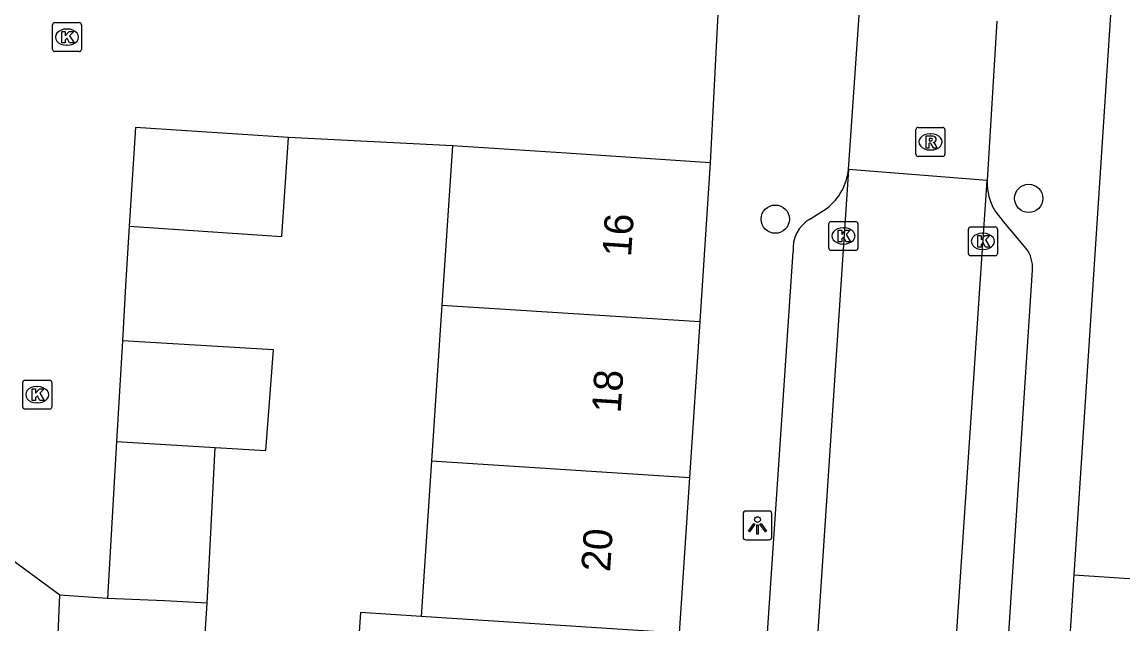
# Model space of a CAD drawing. Extents: x 160356 to 161355, y 381727 to 382845.
# Drawn here: x 160534.35 to 160572.44, y 382168.23 to 382189.04 of the extents above; entities that cross this region are included whole.
import ezdxf

# ---------------------------------------------------------------- set-up
doc = ezdxf.new("R2010")
doc.units = 0
for name, color, linetype in [('IMGEO_Boom', 7, 'Continuous'), ('IMGEO_Kolk', 7, 'Continuous'), ('IMGEO_Lichtpunt', 7, 'Continuous'), ('IMGEO_Pand', 7, 'Continuous'), ('IMGEO_Pand_nummerreeks', 7, 'Continuous'), ('IMGEO_Rijbaan_lokaal_open', 7, 'Continuous'), ('IMGEO_Rioolput', 7, 'Continuous'), ('IMGEO_Voetpad_open', 7, 'Continuous')]:
    doc.layers.add(name, color=color, linetype=linetype)

msp = doc.modelspace()

# ---------------------------------------------------------------- linework, layer by layer
at = {"layer": 'IMGEO_Boom'}
for centre in [(160569.175, 382182.943), (160560.409, 382182.225)]:
    msp.add_circle(centre, 0.489, dxfattribs=at)
at = {"layer": 'IMGEO_Kolk'}
for p, q in [((160535.48, 382189.019), (160536.332, 382189.019)), ((160535.405, 382188.093), (160535.405, 382188.945)), ((160535.893, 382188.799), (160535.918, 382188.799)), ((160536.406, 382188.945), (160536.406, 382188.093)), ((160535.916, 382188.239), (160535.891, 382188.239)), ((160536.332, 382188.019), (160535.48, 382188.019)), ((160562.339, 382182.144), (160563.191, 382182.144)), ((160562.264, 382181.218), (160562.264, 382182.07)), ((160562.752, 382181.924), (160562.777, 382181.924)), ((160563.265, 382182.07), (160563.265, 382181.218)), ((160567.09, 382181.031), (160567.09, 382181.883)), ((160567.165, 382181.957), (160568.017, 382181.957)), ((160568.091, 382181.883), (160568.091, 382181.031)), ((160562.775, 382181.364), (160562.75, 382181.364)), ((160567.578, 382181.737), (160567.603, 382181.737)), ((160563.191, 382181.144), (160562.339, 382181.144)), ((160567.601, 382181.177), (160567.576, 382181.177)), ((160568.017, 382180.957), (160567.165, 382180.957)), ((160534.377, 382175.73), (160534.377, 382176.582)), ((160534.452, 382176.656), (160535.304, 382176.656)), ((160534.865, 382176.436), (160534.89, 382176.436)), ((160535.378, 382176.582), (160535.378, 382175.73)), ((160535.304, 382175.656), (160534.452, 382175.656)), ((160534.888, 382175.876), (160534.863, 382175.876))]:
    msp.add_line(p, q, dxfattribs=at)
for points in [[(160535.48, 382189.019), (160536.332, 382189.019)], [(160535.405, 382188.093), (160535.405, 382188.945)], [(160535.726, 382188.719), (160535.849, 382188.719), (160535.849, 382188.568), (160535.979, 382188.719), (160536.143, 382188.719), (160535.997, 382188.568), (160536.15, 382188.319), (160535.998, 382188.319), (160535.913, 382188.483), (160535.849, 382188.416), (160535.849, 382188.319), (160535.726, 382188.319), (160535.726, 382188.719)], [(160536.406, 382188.945), (160536.406, 382188.093)], [(160536.332, 382188.019), (160535.48, 382188.019)], [(160562.339, 382182.144), (160563.191, 382182.144)], [(160562.264, 382181.218), (160562.264, 382182.07)], [(160562.585, 382181.844), (160562.708, 382181.844), (160562.708, 382181.693), (160562.838, 382181.844), (160563.002, 382181.844), (160562.856, 382181.693), (160563.009, 382181.444), (160562.857, 382181.444), (160562.772, 382181.608), (160562.708, 382181.541), (160562.708, 382181.444), (160562.585, 382181.444), (160562.585, 382181.844)], [(160563.265, 382182.07), (160563.265, 382181.218)], [(160567.09, 382181.031), (160567.09, 382181.883)], [(160567.165, 382181.957), (160568.017, 382181.957)], [(160568.091, 382181.883), (160568.091, 382181.031)], [(160567.411, 382181.657), (160567.534, 382181.657), (160567.534, 382181.506), (160567.664, 382181.657), (160567.828, 382181.657), (160567.682, 382181.506), (160567.835, 382181.257), (160567.683, 382181.257), (160567.598, 382181.421), (160567.534, 382181.354), (160567.534, 382181.257), (160567.411, 382181.257), (160567.411, 382181.657)], [(160563.191, 382181.144), (160562.339, 382181.144)], [(160568.017, 382180.957), (160567.165, 382180.957)], [(160534.377, 382175.73), (160534.377, 382176.582)], [(160534.452, 382176.656), (160535.304, 382176.656)], [(160535.378, 382176.582), (160535.378, 382175.73)], [(160534.698, 382176.356), (160534.821, 382176.356), (160534.821, 382176.205), (160534.951, 382176.356), (160535.115, 382176.356), (160534.969, 382176.205), (160535.122, 382175.956), (160534.97, 382175.956), (160534.885, 382176.12), (160534.821, 382176.053), (160534.821, 382175.956), (160534.698, 382175.956), (160534.698, 382176.356)], [(160535.304, 382175.656), (160534.452, 382175.656)]]:
    msp.add_lwpolyline(points, dxfattribs=at)
for centre, start, end in [((160535.482, 382188.943), 91.552, 178.448), ((160535.482, 382188.943), 91.552, 178.448), ((160536.33, 382188.943), 1.552, 88.448), ((160536.33, 382188.943), 1.552, 88.448), ((160535.482, 382188.095), 181.552, 268.448), ((160535.482, 382188.095), 181.552, 268.448), ((160536.33, 382188.095), 271.552, 358.448), ((160536.33, 382188.095), 271.552, 358.448), ((160562.341, 382182.068), 91.552, 178.448), ((160562.341, 382182.068), 91.552, 178.448), ((160563.189, 382182.068), 1.552, 88.448), ((160563.189, 382182.068), 1.552, 88.448), ((160567.167, 382181.881), 91.552, 178.448), ((160567.167, 382181.881), 91.552, 178.448), ((160568.015, 382181.881), 1.552, 88.448), ((160568.015, 382181.881), 1.552, 88.448), ((160562.341, 382181.22), 181.552, 268.448), ((160562.341, 382181.22), 181.552, 268.448), ((160563.189, 382181.22), 271.552, 358.448), ((160563.189, 382181.22), 271.552, 358.448), ((160567.167, 382181.033), 181.552, 268.448), ((160567.167, 382181.033), 181.552, 268.448), ((160568.015, 382181.033), 271.552, 358.448), ((160568.015, 382181.033), 271.552, 358.448), ((160534.454, 382176.58), 91.552, 178.448), ((160534.454, 382176.58), 91.552, 178.448), ((160535.302, 382176.58), 1.552, 88.448), ((160535.302, 382176.58), 1.552, 88.448), ((160534.454, 382175.732), 181.552, 268.448), ((160534.454, 382175.732), 181.552, 268.448), ((160535.302, 382175.732), 271.552, 358.448), ((160535.302, 382175.732), 271.552, 358.448)]:
    msp.add_arc(centre, 0.0765, start, end, dxfattribs=at)
for centre, major_axis, ratio, start_param, end_param in [((160535.892, 382188.519), (-0.387, 0.002), 0.722429, 4.712389, 7.853982), ((160535.917, 382188.519), (-0.39, 0.002), 0.717154, 1.570796, 4.712389), ((160562.751, 382181.644), (-0.387, 0.002), 0.722429, 4.712389, 7.853982), ((160562.776, 382181.644), (-0.39, 0.002), 0.717154, 1.570796, 4.712389), ((160567.577, 382181.457), (-0.387, 0.002), 0.722429, 4.712389, 7.853982), ((160567.602, 382181.457), (-0.39, 0.002), 0.717154, 1.570796, 4.712389), ((160534.864, 382176.156), (-0.387, 0.002), 0.722429, 4.712389, 7.853982), ((160534.889, 382176.156), (-0.39, 0.002), 0.717154, 1.570796, 4.712389)]:
    msp.add_ellipse(centre, major_axis=major_axis, ratio=ratio, start_param=start_param, end_param=end_param, dxfattribs=at)
at = {"layer": 'IMGEO_Lichtpunt'}
for p, q in [((160559.293, 382172.039), (160559.293, 382171.232)), ((160559.293, 382172.039), (160559.293, 382171.232)), ((160560.195, 382172.134), (160559.387, 382172.134)), ((160560.195, 382172.134), (160559.387, 382172.134)), ((160560.289, 382171.232), (160560.289, 382172.039)), ((160560.289, 382171.232), (160560.289, 382172.039)), ((160559.387, 382171.138), (160560.195, 382171.138)), ((160559.387, 382171.138), (160560.195, 382171.138))]:
    msp.add_line(p, q, dxfattribs=at)
for points in [[(160559.667, 382171.703), (160559.706, 382171.675), (160559.518, 382171.413), (160559.48, 382171.44), (160559.667, 382171.703)], [(160559.769, 382171.655), (160559.816, 382171.655), (160559.816, 382171.333), (160559.769, 382171.333), (160559.769, 382171.655)], [(160559.879, 382171.675), (160559.917, 382171.702), (160560.104, 382171.44), (160560.065, 382171.412), (160559.879, 382171.675)]]:
    msp.add_lwpolyline(points, dxfattribs=at)
msp.add_circle((160559.792, 382171.837), 0.0994, dxfattribs=at)
for centre, start, end in [((160559.387, 382172.039), 90, 180), ((160559.387, 382172.039), 90, 180), ((160560.195, 382172.039), 0, 90), ((160560.195, 382172.039), 0, 90), ((160559.387, 382171.232), 180, 270), ((160559.387, 382171.232), 180, 270), ((160560.195, 382171.232), 270, 0), ((160560.195, 382171.232), 270, 360)]:
    msp.add_arc(centre, 0.0946, start, end, dxfattribs=at)
at = {"layer": 'IMGEO_Pand'}
for points in [[(160543.567, 382185.043), (160538.279, 382185.395), (160538.062, 382181.978)], [(160538.062, 382181.978), (160543.339, 382181.626), (160543.567, 382185.043)], [(160549.242, 382184.764), (160548.875, 382179.253)], [(160558.16, 382184.17), (160553.172, 382184.502), (160549.242, 382184.764)], [(160558.16, 382184.17), (160557.795, 382178.692)], [(160548.875, 382179.253), (160548.516, 382173.864)], [(160548.875, 382179.253), (160557.795, 382178.692)], [(160557.795, 382178.692), (160557.436, 382173.292)], [(160537.822, 382178.018), (160537.621, 382174.536)], [(160541.034, 382174.328), (160542.786, 382174.221), (160543.047, 382177.709), (160537.822, 382178.018)], [(160537.621, 382174.536), (160537.308, 382169.114)], [(160537.621, 382174.536), (160541.034, 382174.328)], [(160540.757, 382168.95), (160540.882, 382171.378), (160541.034, 382174.328)], [(160548.516, 382173.864), (160548.158, 382168.485)], [(160548.516, 382173.864), (160557.436, 382173.292)], [(160535.662, 382169.225), (160529.614, 382173.66)], [(160557.436, 382173.292), (160557.078, 382167.913)], [(160535.429, 382163.878), (160535.662, 382169.225)], [(160537.308, 382169.114), (160535.662, 382169.225)], [(160540.757, 382168.95), (160539.285, 382169.025), (160537.308, 382169.114)], [(160537.919, 382163.722), (160538.919, 382163.66), (160539.154, 382167.099), (160540.624, 382166.999), (160540.757, 382168.95)], [(160548.158, 382168.485), (160546.054, 382168.62), (160545.696, 382163.243), (160546.046, 382163.22)], [(160557.078, 382167.913), (160548.158, 382168.485)]]:
    msp.add_lwpolyline(points, dxfattribs=at)
at = {"layer": 'IMGEO_Rijbaan_lokaal_open'}
for points in [[(160558.444, 382189.759), (160558.16, 382184.17)], [(160562.945, 382183.938), (160563.32, 382189.437)], [(160568.072, 382189.072), (160567.738, 382183.56)], [(160549.242, 382184.764), (160543.567, 382185.043)], [(160562.945, 382183.938), (160560.456, 382146.449)], [(160567.738, 382183.56), (160562.945, 382183.938)], [(160565.301, 382146.8), (160565.486, 382149.584), (160566.437, 382164.19), (160567.561, 382181.023), (160567.738, 382183.56)], [(160538.062, 382181.978), (160537.932, 382179.922), (160537.822, 382178.018)]]:
    msp.add_lwpolyline(points, dxfattribs=at)
at = {"layer": 'IMGEO_Rioolput'}
for p, q in [((160565.275, 382184.47), (160565.275, 382185.322)), ((160565.35, 382185.396), (160566.202, 382185.396)), ((160565.763, 382185.176), (160565.788, 382185.176)), ((160566.276, 382185.322), (160566.276, 382184.47)), ((160565.786, 382184.616), (160565.761, 382184.616)), ((160566.202, 382184.396), (160565.35, 382184.396))]:
    msp.add_line(p, q, dxfattribs=at)
for points in [[(160565.275, 382184.47), (160565.275, 382185.322)], [(160565.35, 382185.396), (160566.202, 382185.396)], [(160566.276, 382185.322), (160566.276, 382184.47)], [(160565.864, 382185.094), (160565.612, 382185.096), (160565.612, 382184.696)], [(160565.612, 382184.696), (160565.736, 382184.696), (160565.736, 382184.858), (160565.747, 382184.858)], [(160565.79, 382185.015), (160565.736, 382185.015), (160565.736, 382184.934)], [(160565.736, 382184.934), (160565.788, 382184.934)], [(160565.794, 382184.829), (160565.865, 382184.696), (160566.005, 382184.696), (160565.94, 382184.822)], [(160566.202, 382184.396), (160565.35, 382184.396)]]:
    msp.add_lwpolyline(points, dxfattribs=at)
for centre, radius, start, end in [((160565.352, 382185.32), 0.0765, 91.552, 178.448), ((160565.352, 382185.32), 0.0765, 91.552, 178.448), ((160566.2, 382185.32), 0.0765, 1.552, 88.448), ((160566.2, 382185.32), 0.0765, 1.552, 88.448), ((160565.746, 382184.805), 0.0533, 26.0293, 88.6989), ((160565.772, 382185.123), 0.19, 274.7715, 282.9687), ((160565.796, 382184.919), 0.0964, 77.0061, 93.1865), ((160565.81, 382184.976), 0.0378, 276.6634, 79.6772), ((160565.863, 382184.984), 0.109, 350.3612, 89.416), ((160565.861, 382184.984), 0.112, 277.5842, 350.9817), ((160565.845, 382184.769), 0.108, 29.5134, 73.7905), ((160565.352, 382184.472), 0.0765, 181.552, 268.448), ((160565.352, 382184.472), 0.0765, 181.552, 268.448), ((160566.2, 382184.472), 0.0765, 271.552, 358.448), ((160566.2, 382184.472), 0.0765, 271.552, 358.448)]:
    msp.add_arc(centre, radius, start, end, dxfattribs=at)
for centre, major_axis, ratio, start_param, end_param in [((160565.762, 382184.896), (-0.387, 0.002), 0.722429, 4.712389, 7.853982), ((160565.787, 382184.896), (-0.39, 0.002), 0.717154, 1.570796, 4.712389)]:
    msp.add_ellipse(centre, major_axis=major_axis, ratio=ratio, start_param=start_param, end_param=end_param, dxfattribs=at)
at = {"layer": 'IMGEO_Voetpad_open'}
for points in [[(160572.766, 382200.922), (160570.733, 382169.923)], [(160561.608, 382182.227), (160562.205, 382182.608)], [(160569.085, 382181.215), (160568.25, 382182.212)], [(160558.907, 382149.631), (160561.024, 382181.097)], [(160567.281, 382149.37), (160569.305, 382180.462)], [(160570.733, 382169.923), (160594.668, 382168.353), (160594.717, 382169.209), (160594.823, 382171.077)], [(160570.733, 382169.923), (160570.594, 382167.804), (160570.578, 382167.565)]]:
    msp.add_lwpolyline(points, dxfattribs=at)
for centre, radius, start, end in [((160560.963, 382184.17), 1.995, 308.4859, 353.3317), ((160569.547, 382183.476), 1.811, 177.3387, 224.2571), ((160562.207, 382181.202), 1.187, 120.2786, 185.0603), ((160568.218, 382180.553), 1.091, 355.218, 37.355)]:
    msp.add_arc(centre, radius, start, end, dxfattribs=at)

# ---------------------------------------------------------------- texts
at = {"layer": 'IMGEO_Pand_nummerreeks'}
for s, p in [('16', (160555.417, 382180.902)), ('18', (160555.057, 382175.503)), ('20', (160554.691, 382170.01))]:
    msp.add_text(s, height=1, rotation=86.1918, dxfattribs=at).set_placement(p)

doc.saveas('drawing.dxf')
